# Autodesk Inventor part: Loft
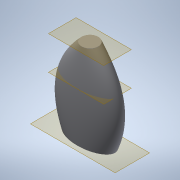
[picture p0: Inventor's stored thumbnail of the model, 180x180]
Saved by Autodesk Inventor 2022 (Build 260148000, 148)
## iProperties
Created: 2013-12
Part Number: Loft
Material: Generic
Document SubType Name: Modeling
Designer: John
Density: 1 g/cm^3
Appearance: Default
Author: John
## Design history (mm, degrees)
sketch "Sketch1" dims "d0" = 38.1, "d1" = 19.05
  geometry: 2 further points; 1 other entity
  constraints: 1 coincident, 2 other
workplane "Work Plane1"
sketch "Sketch2" dims "d3" = 44.45, "d4" = 20.32
  geometry: 2 further points; 1 other entity
  constraints: 1 coincident, 2 other
workplane "Work Plane2"
sketch "Sketch3"
  geometry: C1 r 12.7 at (0, 0); 1 further point
  constraints: 1 centre point, 1 coincident
  dimensions: "d6" = 25.4 diameter of C1
loft "Loft1" sketch "Sketch3" dims "d7" = 0, "d8" = 90 deg, "d9" = 0, "d10" = 90 deg, "d11" = 0, "d12" = 90 deg
body "Solid1"
other parameters: "d2" = 76.2, "d5" = 50.8
